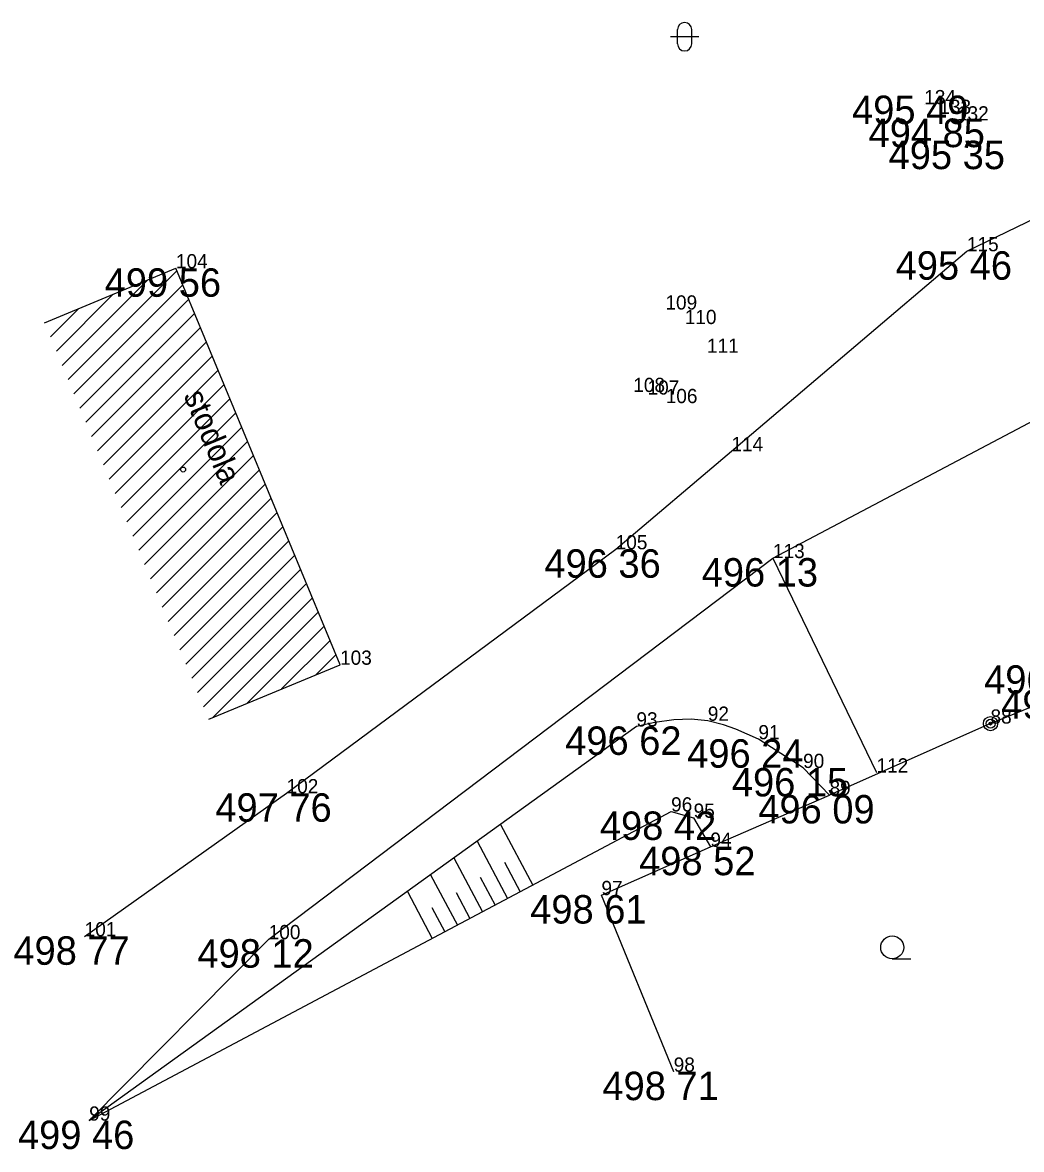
# Model space of a CAD drawing. Extents: x -559180 to -551373, y -1076947 to -1072071.
# Drawn here: x -553524.18 to -553489.06, y -1076698.48 to -1076658.86 of the extents above; entities that cross this region are included whole.
import ezdxf

# ---------------------------------------------------------------- set-up
doc = ezdxf.new("R2010")
doc.units = 0
for name, color, linetype in [('12_PLOTY', 7, 'Continuous'), ('14_BUDOVY', 7, 'Continuous'), ('17_KOMUNIKACE', 7, 'Continuous'), ('1_VODA_ZN', 7, 'Continuous'), ('26_SRAFY', 7, 'Continuous'), ('27_HRANA_PATA', 7, 'Continuous'), ('32', 7, 'Continuous'), ('3_BODY', 7, 'Continuous'), ('45_ZN_KULTURY', 7, 'Continuous'), ('47_ZN_STAV_OBJ$', 7, 'Continuous'), ('52_POPIS_UCELOVY', 7, 'Continuous'), ('6_VYSKY', 7, 'Continuous')]:
    doc.layers.add(name, color=color, linetype=linetype)

# ---------------------------------------------------------------- blocks, each defined once
blk = doc.blocks.new('POINT_DISPLAY')
blk.add_line((0, 0), (0, 0))
blk = doc.blocks.new('SL')
at = {"layer": '47_ZN_STAV_OBJ$'}
for radius in [0.25, 0.158, 0.05]:
    blk.add_circle((0, 0), radius, dxfattribs=at)
blk = doc.blocks.new('BZ')
at = {"layer": '47_ZN_STAV_OBJ$'}
blk.add_circle((0, 0), 0.0875, dxfattribs=at)
blk = doc.blocks.new('ZAHRAD')
at = {"layer": '45_ZN_KULTURY'}
blk.add_line((0, 0), (0.65, 0.003), dxfattribs=at)
blk.add_circle((0, 0.403), 0.403, dxfattribs=at)
blk = doc.blocks.new('NEPLOD')
at = {"layer": '45_ZN_KULTURY'}
for p, q in [((0.519, 0.01), (-0.481, 0.01)), ((-0.231, -0.24), (-0.231, 0.26)), ((0.269, -0.24), (0.269, 0.26))]:
    blk.add_line(p, q, dxfattribs=at)
for centre, start, end in [((0.019, 0.26), 0, 180), ((0.019, -0.24), 180, 0)]:
    blk.add_arc(centre, 0.25, start, end, dxfattribs=at)

msp = doc.modelspace()

# ---------------------------------------------------------------- linework, layer by layer
at = {"layer": '12_PLOTY'}
for p, q in [((-553490.15, -1076683.51), (-553487.27, -1076682.33)), ((-553490.15, -1076683.51), (-553495.81, -1076686.02)), ((-553500, -1076687.84), (-553495.81, -1076686.02)), ((-553503.83, -1076689.54), (-553500, -1076687.84)), ((-553501.29, -1076695.75), (-553503.83, -1076689.54))]:
    msp.add_line(p, q, dxfattribs=at)
at = {"layer": '14_BUDOVY'}
for p, q in [((-553523.41, -1076669.412), (-553518.79, -1076667.5)), ((-553513.02, -1076681.44), (-553518.79, -1076667.5)), ((-553517.64, -1076683.352), (-553513.02, -1076681.44))]:
    msp.add_line(p, q, dxfattribs=at)
at = {"layer": '17_KOMUNIKACE'}
for p, q in [((-553490.98, -1076666.9), (-553482.78, -1076662.93)), ((-553499.26, -1076673.93), (-553490.98, -1076666.9)), ((-553497.8, -1076677.69), (-553484.06, -1076670.43)), ((-553503.33, -1076677.38), (-553499.26, -1076673.93)), ((-553514.9, -1076685.96), (-553503.33, -1076677.38)), ((-553515.53, -1076691.09), (-553497.8, -1076677.69)), ((-553497.8, -1076677.69), (-553494.16, -1076685.23)), ((-553522, -1076690.99), (-553514.9, -1076685.96)), ((-553515.53, -1076691.09), (-553521.84, -1076697.47))]:
    msp.add_line(p, q, dxfattribs=at)
at = {"layer": '26_SRAFY'}
for p, q in [((-553507.379, -1076687.053), (-553506.246, -1076689.185)), ((-553508.198, -1076687.643), (-553507.129, -1076689.654)), ((-553509.017, -1076688.233), (-553508.012, -1076690.124)), ((-553507.238, -1076688.384), (-553506.688, -1076689.42)), ((-553509.836, -1076688.823), (-553508.895, -1076690.593)), ((-553508.089, -1076688.913), (-553507.571, -1076689.889)), ((-553510.655, -1076689.413), (-553509.779, -1076691.062)), ((-553508.94, -1076689.443), (-553508.454, -1076690.358)), ((-553509.791, -1076689.973), (-553509.337, -1076690.827))]:
    msp.add_line(p, q, dxfattribs=at)
at = {"layer": '27_HRANA_PATA'}
for p, q in [((-553502.6, -1076683.61), (-553521.84, -1076697.47)), ((-553496.74, -1076685.07), (-553498.31, -1076684.06)), ((-553495.81, -1076686.02), (-553496.74, -1076685.07)), ((-553521.84, -1076697.47), (-553501.38, -1076686.6)), ((-553501.38, -1076686.6), (-553500.59, -1076686.82)), ((-553500.59, -1076686.82), (-553500, -1076687.84))]:
    msp.add_line(p, q, dxfattribs=at)
for points in [[(-553500.09, -1076683.41), (-553500.676, -1076683.355), (-553501.283, -1076683.38), (-553501.952, -1076683.467), (-553502.6, -1076683.61)], [(-553498.31, -1076684.06), (-553499.1, -1076683.707), (-553499.544, -1076683.548), (-553500.09, -1076683.41)]]:
    msp.add_lwpolyline(points, dxfattribs=at)
at = {"layer": '32'}
for p, q in [((-553522.582, -1076671.412), (-553518.755, -1076667.585)), ((-553522.789, -1076670.912), (-553519.791, -1076667.914)), ((-553522.375, -1076671.913), (-553518.548, -1076668.085)), ((-553522.996, -1076670.412), (-553520.997, -1076668.413)), ((-553522.168, -1076672.413), (-553518.341, -1076668.585)), ((-553523.203, -1076669.912), (-553522.204, -1076668.913)), ((-553521.961, -1076672.913), (-553518.134, -1076669.085)), ((-553521.754, -1076673.413), (-553517.927, -1076669.586)), ((-553521.547, -1076673.913), (-553517.72, -1076670.086)), ((-553521.34, -1076674.413), (-553517.513, -1076670.586)), ((-553521.133, -1076674.913), (-553517.306, -1076671.086)), ((-553520.926, -1076675.413), (-553517.099, -1076671.586)), ((-553520.719, -1076675.913), (-553516.892, -1076672.086)), ((-553520.512, -1076676.413), (-553516.685, -1076672.586)), ((-553520.305, -1076676.914), (-553516.478, -1076673.086)), ((-553520.098, -1076677.414), (-553516.271, -1076673.586)), ((-553519.891, -1076677.914), (-553516.064, -1076674.087)), ((-553519.684, -1076678.414), (-553515.857, -1076674.587)), ((-553519.477, -1076678.914), (-553515.65, -1076675.087)), ((-553519.27, -1076679.414), (-553515.443, -1076675.587)), ((-553519.063, -1076679.914), (-553515.236, -1076676.087)), ((-553518.856, -1076680.414), (-553515.029, -1076676.587)), ((-553518.649, -1076680.914), (-553514.822, -1076677.087)), ((-553518.442, -1076681.415), (-553514.615, -1076677.587)), ((-553518.235, -1076681.915), (-553514.408, -1076678.087)), ((-553518.028, -1076682.415), (-553514.201, -1076678.587)), ((-553517.821, -1076682.915), (-553513.994, -1076679.088)), ((-553517.488, -1076683.289), (-553513.787, -1076679.588)), ((-553516.282, -1076682.79), (-553513.58, -1076680.088)), ((-553515.075, -1076682.291), (-553513.373, -1076680.588)), ((-553513.869, -1076681.791), (-553513.166, -1076681.088))]:
    msp.add_line(p, q, dxfattribs=at)

# ---------------------------------------------------------------- block references
at = {"layer": '1_VODA_ZN'}
for p in [(-553492.48, -1076661.73), (-553491.95, -1076662.07), (-553491.33, -1076662.3), (-553490.98, -1076666.9), (-553518.79, -1076667.5), (-553499.26, -1076673.93), (-553503.33, -1076677.38), (-553497.8, -1076677.69), (-553513.02, -1076681.44), (-553500.09, -1076683.41), (-553490.15, -1076683.51), (-553502.6, -1076683.61), (-553498.31, -1076684.06), (-553496.74, -1076685.07), (-553494.16, -1076685.23), (-553514.9, -1076685.96), (-553495.81, -1076686.02), (-553501.38, -1076686.6), (-553500.59, -1076686.82), (-553500, -1076687.84), (-553503.83, -1076689.54), (-553522, -1076690.99), (-553515.53, -1076691.09), (-553501.29, -1076695.75), (-553521.84, -1076697.47)]:
    msp.add_blockref('POINT_DISPLAY', p, dxfattribs=at)
at = {"layer": '32'}
msp.add_blockref('POINT_DISPLAY', (-553523.41, -1076669.412), dxfattribs=at)
at = {"layer": '45_ZN_KULTURY'}
for name, p in [('NEPLOD', (-553500.926, -1076659.367)), ('ZAHRAD', (-553493.607, -1076691.783))]:
    msp.add_blockref(name, p, dxfattribs=at)
at = {"layer": '47_ZN_STAV_OBJ$'}
for name, p in [('BZ', (-553518.538, -1076674.576)), ('SL', (-553490.15, -1076683.51))]:
    msp.add_blockref(name, p, dxfattribs=at)

# ---------------------------------------------------------------- texts
at = {"layer": '3_BODY'}
for s, p in [('134', (-553492.48, -1076661.73)), ('133', (-553491.95, -1076662.07)), ('132', (-553491.33, -1076662.3)), ('115', (-553490.98, -1076666.9)), ('104', (-553518.79, -1076667.5)), ('109', (-553501.58, -1076668.95)), ('110', (-553500.9, -1076669.46)), ('111', (-553500.12, -1076670.47)), ('108', (-553502.71, -1076671.85)), ('107', (-553502.21, -1076671.94)), ('106', (-553501.57, -1076672.24)), ('114', (-553499.26, -1076673.93)), ('105', (-553503.33, -1076677.38)), ('113', (-553497.8, -1076677.69)), ('103', (-553513.02, -1076681.44)), ('93', (-553502.6, -1076683.61)), ('92', (-553500.09, -1076683.41)), ('88', (-553490.15, -1076683.51)), ('91', (-553498.31, -1076684.06)), ('90', (-553496.74, -1076685.07)), ('112', (-553494.16, -1076685.23)), ('102', (-553514.9, -1076685.96)), ('89', (-553495.81, -1076686.02)), ('96', (-553501.38, -1076686.6)), ('95', (-553500.59, -1076686.82)), ('94', (-553500, -1076687.84)), ('97', (-553503.83, -1076689.54)), ('101', (-553522, -1076690.99)), ('100', (-553515.53, -1076691.09)), ('98', (-553501.29, -1076695.75)), ('99', (-553521.84, -1076697.47))]:
    msp.add_text(s, height=0.5, dxfattribs=at).set_placement(p)
at = {"layer": '52_POPIS_UCELOVY'}
msp.add_text('stodola', height=0.8, rotation=292.4855, dxfattribs=at).set_placement((-553518.531, -1076671.966))
at = {"layer": '6_VYSKY'}
for s, p in [('495 49', (-553495.018, -1076662.426)), ('494 85', (-553494.438, -1076663.239)), ('495 35', (-553493.733, -1076664.012)), ('495 46', (-553493.485, -1076667.9)), ('499 56', (-553521.295, -1076668.5)), ('496 36', (-553505.835, -1076678.38)), ('496 13', (-553500.305, -1076678.69)), ('496 40', (-553490.375, -1076682.46)), ('496 39', (-553489.775, -1076683.33)), ('496 62', (-553505.105, -1076684.61)), ('496 24', (-553500.815, -1076685.06)), ('496 15', (-553499.245, -1076686.07)), ('497 76', (-553517.405, -1076686.96)), ('496 09', (-553498.315, -1076687.02)), ('498 42', (-553503.885, -1076687.6)), ('498 52', (-553502.505, -1076688.84)), ('498 61', (-553506.335, -1076690.54)), ('498 77', (-553524.505, -1076691.99)), ('498 12', (-553518.035, -1076692.09)), ('498 71', (-553503.795, -1076696.75)), ('499 46', (-553524.345, -1076698.47))]:
    msp.add_text(s, height=1, dxfattribs=at).set_placement(p)

doc.saveas('drawing.dxf')
